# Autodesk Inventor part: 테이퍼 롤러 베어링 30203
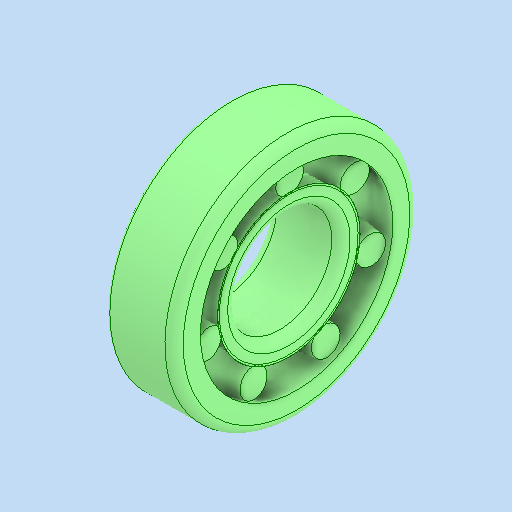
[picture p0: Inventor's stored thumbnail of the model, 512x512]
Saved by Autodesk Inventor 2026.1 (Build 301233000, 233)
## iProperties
Created: 2026-01
Part Number: 테이퍼 롤러 베어링 30203
Material: 강철, 연강
Description: 테이퍼 롤러 베어링
Document SubType Name: Modeling
Designer: PC-30
Density: 7.85 g/cm^3
Appearance: 기본값
Author: jhkim
Sending System: Autodesk Inventor 2026
Preprocessor: ST-DEVELOPER v20.1
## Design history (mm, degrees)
feature "Solid1"
feature "Solid1:1"
node "솔리드1"
node "솔리드2"
